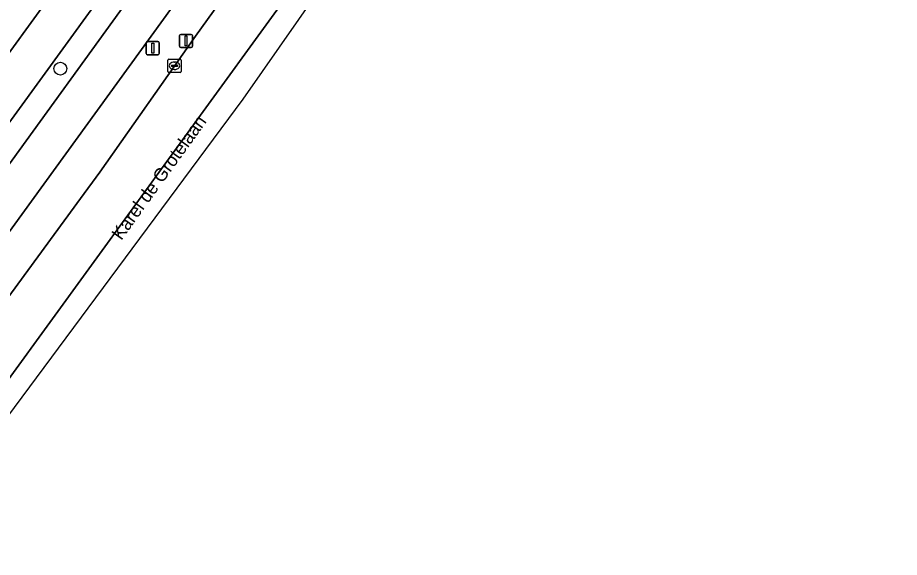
# Model space of a CAD drawing. Extents: x 159674 to 160531, y 382172 to 382904.
# Drawn here: x 160339.1 to 160406.3, y 382498.7 to 382539.8 of the extents above; entities that cross this region are included whole.
import ezdxf

# ---------------------------------------------------------------- set-up
doc = ezdxf.new("R2010")
doc.units = 0
for name, color, linetype in [('IMGEO_Berm_groen', 7, 'Continuous'), ('IMGEO_Boom', 7, 'Continuous'), ('IMGEO_Fietspad_gesloten', 7, 'Continuous'), ('IMGEO_Groenvoorziening', 7, 'Continuous'), ('IMGEO_Kolk', 7, 'Continuous'), ('IMGEO_Lichtmast', 7, 'Continuous'), ('IMGEO_Openbare_ruimte_label', 7, 'Continuous'), ('IMGEO_Rijbaan_lokaal_gesloten', 7, 'Continuous'), ('IMGEO_Voetpad_open', 7, 'Continuous')]:
    doc.layers.add(name, color=color, linetype=linetype)

msp = doc.modelspace()

# ---------------------------------------------------------------- linework, layer by layer
at = {"layer": 'IMGEO_Berm_groen'}
for points in [[(160349.002, 382543.246), (160398.827, 382611.342), (160398.73, 382611.41), (160397.047, 382612.59), (160360.539, 382562.246), (160346.84, 382543.397), (160315.294, 382500), (160291.256, 382466.928), (160255.648, 382417.937), (160257.187, 382416.772), (160266.645, 382429.855), (160311.53, 382491.554)], [(160343.873, 382526.012), (160345.353, 382528.03), (160352.635, 382538.399), (160362.897, 382552.659), (160374.83, 382569.169), (160378.396, 382574.452), (160390.705, 382592.122), (160401.931, 382608.929), (160401.131, 382609.485), (160351.662, 382541.731), (160259.615, 382414.865), (160260.653, 382414.245), (160291.094, 382453.563), (160297.701, 382462.662), (160324.815, 382500)]]:
    msp.add_lwpolyline(points, close=True, dxfattribs=at)
at = {"layer": 'IMGEO_Boom'}
msp.add_circle((160342.338, 382535.914), 0.489, dxfattribs=at)
at = {"layer": 'IMGEO_Fietspad_gesloten'}
msp.add_lwpolyline([(160351.662, 382541.731), (160401.131, 382609.485), (160403.23, 382612.508), (160404.299, 382614.103), (160401.904, 382615.599), (160398.827, 382611.342), (160349.002, 382543.246), (160311.53, 382491.554), (160266.645, 382429.855), (160257.187, 382416.772), (160254.673, 382413.295), (160254.433, 382412.964), (160257.305, 382411.797), (160259.615, 382414.865)], close=True, dxfattribs=at)
at = {"layer": 'IMGEO_Groenvoorziening'}
msp.add_lwpolyline([(160293.252, 382483.855), (160291.445, 382481.395), (160295.603, 382478.257), (160311.42, 382500), (160344.923, 382546.056)], dxfattribs=at)
at = {"layer": 'IMGEO_Kolk'}
for p, q in [((160350.54, 382535.703), (160350.54, 382536.555)), ((160350.615, 382536.629), (160351.467, 382536.629)), ((160350.799, 382536.123), (160350.799, 382536.135)), ((160351.237, 382536.086), (160350.839, 382536.086)), ((160350.842, 382536.172), (160351.24, 382536.172)), ((160351.028, 382536.409), (160351.053, 382536.409)), ((160351.283, 382536.135), (160351.283, 382536.123)), ((160351.541, 382536.555), (160351.541, 382535.703)), ((160351.467, 382535.629), (160350.615, 382535.629)), ((160351.051, 382535.849), (160351.026, 382535.849))]:
    msp.add_line(p, q, dxfattribs=at)
for points in [[(160350.54, 382535.703), (160350.54, 382536.555)], [(160350.615, 382536.629), (160351.467, 382536.629)], [(160351.541, 382536.555), (160351.541, 382535.703)], [(160351.467, 382535.629), (160350.615, 382535.629)]]:
    msp.add_lwpolyline(points, dxfattribs=at)
for centre, radius, start, end in [((160350.617, 382536.553), 0.0765, 91.55205, 178.44795), ((160350.617, 382536.553), 0.0765, 91.55205, 178.44795), ((160350.839, 382536.132), 0.0403, 85.87752, 175.75265), ((160350.836, 382536.122), 0.0366, 178.93798, 274.71019), ((160351.24, 382536.129), 0.043, 264.86636, 352.45326), ((160351.244, 382536.134), 0.0386, 1.73085, 96.63898), ((160351.465, 382536.553), 0.0765, 1.55205, 88.44795), ((160351.465, 382536.553), 0.0765, 1.55205, 88.44795), ((160350.617, 382535.705), 0.0765, 181.55205, 268.44795), ((160350.617, 382535.705), 0.0765, 181.55205, 268.44795), ((160351.465, 382535.705), 0.0765, 271.55205, 358.44795), ((160351.465, 382535.705), 0.0765, 271.55205, 358.44795)]:
    msp.add_arc(centre, radius, start, end, dxfattribs=at)
for centre, major_axis, ratio, start_param, end_param in [((160351.027, 382536.129), (-0.387, 0.002), 0.722429, 4.712389, 7.853982), ((160351.052, 382536.129), (-0.39, 0.002), 0.717154, 1.570796, 4.712389)]:
    msp.add_ellipse(centre, major_axis=major_axis, ratio=ratio, start_param=start_param, end_param=end_param, dxfattribs=at)
at = {"layer": 'IMGEO_Lichtmast'}
for p, q in [((160351.421, 382537.626), (160351.421, 382538.426)), ((160351.421, 382538.426), (160351.421, 382537.626)), ((160351.521, 382538.526), (160352.311, 382538.526)), ((160352.311, 382538.526), (160351.521, 382538.526)), ((160352.411, 382538.426), (160352.411, 382537.626)), ((160352.411, 382537.626), (160352.411, 382538.426)), ((160348.884, 382537.076), (160348.884, 382537.876)), ((160348.884, 382537.876), (160348.884, 382537.076)), ((160348.984, 382537.976), (160349.774, 382537.976)), ((160349.774, 382537.976), (160348.984, 382537.976)), ((160349.874, 382537.876), (160349.874, 382537.076)), ((160349.874, 382537.076), (160349.874, 382537.876)), ((160352.311, 382537.526), (160351.521, 382537.526)), ((160351.521, 382537.526), (160352.311, 382537.526)), ((160349.774, 382536.976), (160348.984, 382536.976)), ((160348.984, 382536.976), (160349.774, 382536.976))]:
    msp.add_line(p, q, dxfattribs=at)
for points in [[(160351.841, 382538.401), (160351.991, 382538.401), (160351.991, 382537.651), (160351.841, 382537.651), (160351.841, 382538.401)], [(160349.304, 382537.851), (160349.454, 382537.851), (160349.454, 382537.101), (160349.304, 382537.101), (160349.304, 382537.851)]]:
    msp.add_lwpolyline(points, dxfattribs=at)
for centre, start, end in [((160351.521, 382538.426), 90, 180), ((160351.521, 382538.426), 90, 180), ((160352.311, 382538.426), 0, 90), ((160352.311, 382538.426), 360, 90), ((160348.984, 382537.876), 90, 180), ((160348.984, 382537.876), 90, 180), ((160349.774, 382537.876), 0, 90), ((160349.774, 382537.876), 360, 90), ((160351.521, 382537.626), 180, 270), ((160351.521, 382537.626), 180, 270), ((160352.311, 382537.626), 270, 0), ((160352.311, 382537.626), 270, 0), ((160348.984, 382537.076), 180, 270), ((160348.984, 382537.076), 180, 270), ((160349.774, 382537.076), 270, 0), ((160349.774, 382537.076), 270, 0)]:
    msp.add_arc(centre, 0.1, start, end, dxfattribs=at)
at = {"layer": 'IMGEO_Rijbaan_lokaal_gesloten'}
msp.add_lwpolyline([(160338.352, 382512.2), (160363.785, 382547.168), (160368.394, 382553.547), (160375.19, 382563.12), (160381.894, 382572.757), (160386.34, 382579.205), (160392.452, 382588.267), (160403.96, 382605.241), (160404.808, 382606.478), (160401.931, 382608.929), (160390.705, 382592.122), (160378.396, 382574.452), (160374.83, 382569.169), (160362.897, 382552.659), (160352.635, 382538.399), (160345.353, 382528.03), (160343.873, 382526.012), (160324.815, 382500)], dxfattribs=at)
msp.add_lwpolyline([(160265.215, 382410.896), (160356.278, 382533.594), (160406.309, 382605.199), (160404.808, 382606.478), (160403.96, 382605.241), (160392.452, 382588.267), (160386.34, 382579.205), (160381.894, 382572.757), (160375.19, 382563.12), (160368.394, 382553.547), (160363.785, 382547.168), (160338.352, 382512.2), (160312.946, 382477.26), (160301.422, 382461.465), (160294.406, 382451.971), (160280.167, 382433.302), (160272.383, 382423.339), (160263.586, 382412.092)], close=True, dxfattribs=at)
at = {"layer": 'IMGEO_Voetpad_open'}
for points in [[(160401.023, 382623.483), (160399.135, 382620.521), (160346.474, 382548.259), (160344.923, 382546.056), (160311.42, 382500), (160295.603, 382478.257), (160293.955, 382476.039), (160288.608, 382468.68), (160248.967, 382414.122), (160246.396, 382412.259)], [(160254.433, 382412.964), (160254.673, 382413.295), (160257.187, 382416.772), (160255.648, 382417.937), (160291.256, 382466.928), (160315.294, 382500), (160346.84, 382543.397), (160360.539, 382562.246), (160397.047, 382612.59)]]:
    msp.add_lwpolyline(points, dxfattribs=at)

# ---------------------------------------------------------------- texts
at = {"layer": 'IMGEO_Openbare_ruimte_label'}
msp.add_text('Karel de Grotelaan', height=1, rotation=54.3224, dxfattribs=at).set_placement((160346.98, 382522.773))

doc.saveas('drawing.dxf')
